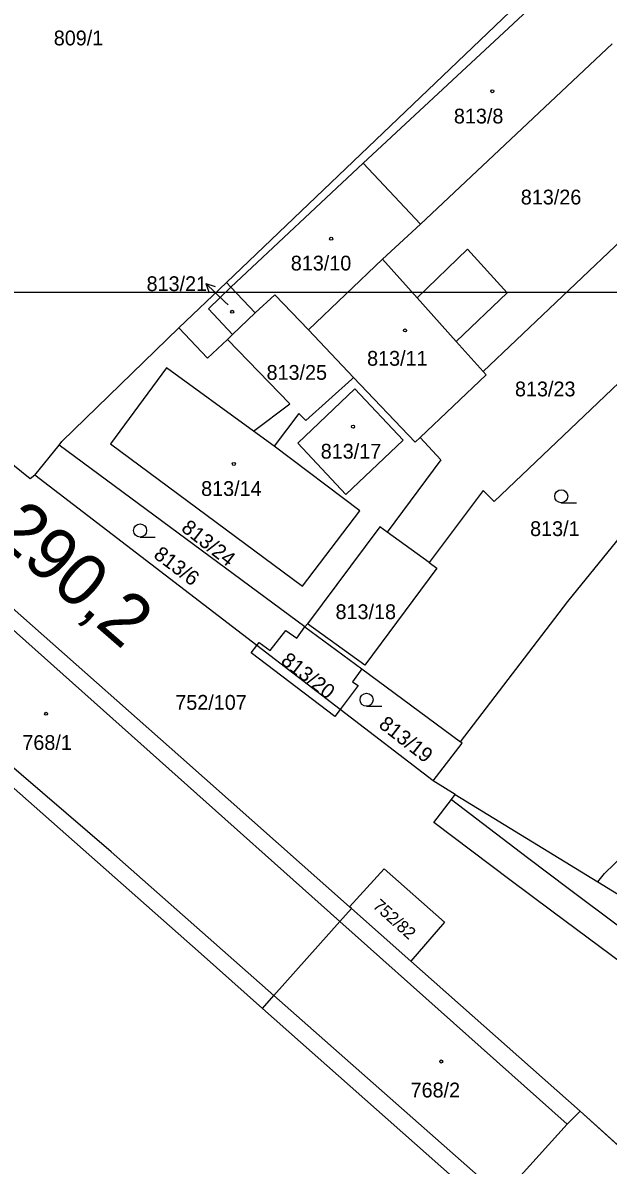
# Model space of a CAD drawing. Extents: x -496682 to -495907, y -1088575 to -1088018.
# Drawn here: x -496396.5 to -496329.2, y -1088264.6 to -1088133.3 of the extents above; entities that cross this region are included whole.
import ezdxf

# ---------------------------------------------------------------- set-up
doc = ezdxf.new("R2010")
doc.units = 0
for name, color, linetype in [('Hranice parcel', 7, 'Continuous'), ('Parcelní čísla', 7, 'Continuous'), ('Pop  PČ popisy', 7, 'Continuous'), ('Vnitřní kresba', 7, 'Continuous'), ('Vrstva 54', 7, 'Continuous'), ('Vrstva 63', 7, 'Continuous'), ('Vrstva 7', 7, 'Continuous'), ('Značky budov', 7, 'Continuous'), ('Značky kultur', 7, 'Continuous')]:
    doc.layers.add(name, color=color, linetype=linetype)

msp = doc.modelspace()

# ---------------------------------------------------------------- linework, layer by layer
at = {"layer": 'Hranice parcel'}
for p, q in [((-496373.06, -1088163.12), (-496321.41, -1088113.75)), ((-496333.69, -1088127.43), (-496357.36, -1088149.42)), ((-496350.76, -1088156.43), (-496328.71, -1088135.71)), ((-496357.36, -1088149.42), (-496372.55, -1088163.66)), ((-496357.36, -1088149.42), (-496350.76, -1088156.43)), ((-496355.12, -1088160.45), (-496350.76, -1088156.43)), ((-496363.63, -1088168.58), (-496355.12, -1088160.45)), ((-496372.55, -1088163.66), (-496373.06, -1088163.12)), ((-496372.55, -1088163.66), (-496369.75, -1088166.63)), ((-496372.37, -1088169.12), (-496369.75, -1088166.63)), ((-496363.63, -1088168.58), (-496358.44, -1088174.04)), ((-496367.58, -1088181.95), (-496369.94, -1088180.21)), ((-496395.1, -1088185.29), (-496392.28, -1088181.83)), ((-496364.03, -1088202.7), (-496392.28, -1088181.83)), ((-496369.57, -1088204.88), (-496395.1, -1088185.29)), ((-496349.76, -1088195.32), (-496354.58, -1088191.83)), ((-496363.73, -1088202.36), (-496364.03, -1088202.7)), ((-496364.03, -1088202.7), (-496357.48, -1088207.54)), ((-496360, -1088212.22), (-496369.57, -1088204.88)), ((-496357.48, -1088207.54), (-496346.16, -1088215.94)), ((-496349.3, -1088220.43), (-496360, -1088212.22)), ((-496346.76, -1088221.99), (-496349.3, -1088220.43)), ((-496347.19, -1088222.58), (-496346.76, -1088221.99)), ((-496346.76, -1088221.99), (-496330.37, -1088232.05)), ((-496358.69, -1088235.08), (-496358.91, -1088234.89)), ((-496358.69, -1088235.08), (-496351.85, -1088241.15)), ((-496351.85, -1088241.15), (-496332.38, -1088258.39)), ((-496325.94, -1088264.24), (-496332.38, -1088258.39))]:
    msp.add_line(p, q, dxfattribs=at)
for points in [[(-496395.1, -1088185.29), (-496395.64, -1088185.72), (-496443.22, -1088147.27)], [(-496317.24, -1088148.77), (-496320.78, -1088151.75), (-496343.54, -1088173.37)], [(-496343.54, -1088173.37), (-496346.64, -1088169.91), (-496340.77, -1088164.33), (-496345.36, -1088159.28), (-496351.12, -1088164.91), (-496355.12, -1088160.45)], [(-496392.28, -1088181.83), (-496391.98, -1088181.42), (-496378.53, -1088168.35), (-496373.06, -1088163.12)], [(-496304.04, -1088162.67), (-496318.49, -1088178.29), (-496324.77, -1088171.65), (-496342.29, -1088188.3), (-496343.55, -1088187.04), (-496349.76, -1088195.32)], [(-496372.55, -1088163.66), (-496375.14, -1088166.17), (-496372.37, -1088169.12)], [(-496369.75, -1088166.63), (-496367.5, -1088164.53), (-496363.63, -1088168.58)], [(-496436.18, -1088166.94), (-496429.51, -1088172.39), (-496378.3, -1088217.72), (-496358.91, -1088234.89)], [(-496369.94, -1088180.21), (-496365.78, -1088177.09), (-496372.95, -1088169.67), (-496372.37, -1088169.12)], [(-496369.94, -1088180.21), (-496379.95, -1088172.96), (-496386.4, -1088181.69), (-496364.31, -1088198.06), (-496357.74, -1088189.38), (-496367.58, -1088181.95)], [(-496358.44, -1088174.04), (-496358.66, -1088174.24), (-496363.93, -1088178.99), (-496364.72, -1088178.18), (-496367.58, -1088181.95)], [(-496358.44, -1088174.04), (-496351.36, -1088181.47), (-496350.8, -1088180.95)], [(-496350.8, -1088180.95), (-496343.21, -1088173.74), (-496343.54, -1088173.37)], [(-496358.3, -1088175.34), (-496364.87, -1088181.6), (-496359.32, -1088187.51), (-496352.73, -1088181.25), (-496358.3, -1088175.34)], [(-496368.91, -1088246.59), (-496375.97, -1088240.32), (-496428.63, -1088193.79), (-496444.11, -1088180.1)], [(-496346.16, -1088215.94), (-496333.82, -1088199.82), (-496318.2, -1088180.61)], [(-496350.8, -1088180.95), (-496348.4, -1088183.52), (-496354.58, -1088191.83)], [(-496354.58, -1088191.83), (-496355.42, -1088191.22), (-496363.73, -1088202.36)], [(-496349.76, -1088195.32), (-496348.88, -1088195.96), (-496357.15, -1088207.11), (-496363.73, -1088202.36)], [(-496330.37, -1088232.05), (-496329.58, -1088231.08), (-496327.35, -1088228.88), (-496319.53, -1088220.58), (-496313.61, -1088214.48), (-496300.1, -1088201.57), (-496296.45, -1088198.31)], [(-496369.57, -1088204.88), (-496369.28, -1088204.51), (-496368.03, -1088205.43), (-496366.23, -1088203.15), (-496364.97, -1088204.01), (-496364.03, -1088202.7)], [(-496357.48, -1088207.54), (-496358.57, -1088209.03), (-496357.92, -1088209.48), (-496360, -1088212.22)], [(-496349.3, -1088220.43), (-496345.96, -1088216.09), (-496346.16, -1088215.94)], [(-496313.9, -1088251.57), (-496335.64, -1088235.39), (-496340.47, -1088231.82), (-496349.2, -1088225.23), (-496347.19, -1088222.58)], [(-496347.19, -1088222.58), (-496338.46, -1088229.24), (-496333.64, -1088232.87), (-496316.4, -1088245.74), (-496315, -1088246.3), (-496313.02, -1088246.35), (-496311.19, -1088245.56), (-496310.18, -1088244.79)], [(-496358.91, -1088234.89), (-496354.93, -1088230.54), (-496348.01, -1088236.66), (-496351.85, -1088241.15)], [(-496330.37, -1088232.05), (-496312.02, -1088243.31), (-496311.81, -1088243.59)], [(-496368.91, -1088246.59), (-496367.6, -1088245.11), (-496360.03, -1088236.59), (-496358.69, -1088235.08)], [(-496332.38, -1088258.39), (-496333.89, -1088259.9), (-496341.4, -1088268.22), (-496342.71, -1088269.83), (-496368.91, -1088246.59)]]:
    msp.add_lwpolyline(points, dxfattribs=at)
at = {"layer": 'Pop  PČ popisy'}
for p, q in [((-496373.26, -1088165.34), (-496375.42, -1088163.26)), ((-496375.42, -1088163.26), (-496374.35, -1088163.59)), ((-496375.42, -1088163.26), (-496375.05, -1088164.31)), ((-496372.87, -1088165.71), (-496373.26, -1088165.34))]:
    msp.add_line(p, q, dxfattribs=at)
at = {"layer": 'Vnitřní kresba'}
for p, q in [((-496351.12, -1088164.91), (-496346.64, -1088169.91)), ((-496375.24, -1088171.83), (-496378.53, -1088168.35)), ((-496372.95, -1088169.67), (-496375.24, -1088171.83)), ((-496360.03, -1088236.59), (-496407.27, -1088194.48)), ((-496386.33, -1088228.59), (-496415.31, -1088203.69)), ((-496370.22, -1088205.69), (-496369.57, -1088204.88)), ((-496360.6, -1088213.02), (-496370.22, -1088205.69)), ((-496360, -1088212.22), (-496360.6, -1088213.02)), ((-496386.33, -1088228.59), (-496367.6, -1088245.11)), ((-496360.03, -1088236.59), (-496333.89, -1088259.9)), ((-496367.6, -1088245.11), (-496341.4, -1088268.22))]:
    msp.add_line(p, q, dxfattribs=at)
at = {"layer": 'Vrstva 54'}
msp.add_lwpolyline([(-496428.63, -1088193.79), (-496375.97, -1088240.32), (-496368.91, -1088246.59), (-496342.71, -1088269.83), (-496341.4, -1088268.22), (-496333.89, -1088259.9), (-496332.38, -1088258.39), (-496325.94, -1088264.24), (-496332.44, -1088271.21), (-496324.32, -1088278.18), (-496327.63, -1088281.05), (-496295.37, -1088310.06), (-496296.07, -1088310.84), (-496290.49, -1088315.87), (-496286.66, -1088311.63), (-496280.68, -1088316.78), (-496283.68, -1088320.49), (-496250.52, -1088349.65), (-496235.04, -1088333.66)], dxfattribs=at)
at = {"layer": 'Vrstva 63'}
msp.add_lwpolyline([(-496137.35, -1088164.24), (-496137.35, -1088461.24), (-496557.35, -1088461.24), (-496557.35, -1088164.24)], close=True, dxfattribs=at)
at = {"layer": 'Značky budov'}
for centre in [(-496342.5, -1088141.14), (-496361.02, -1088158.1), (-496372.4, -1088166.5), (-496352.53, -1088168.64), (-496358.51, -1088179.71), (-496372.21, -1088183.99), (-496393.79, -1088212.71), (-496348.37, -1088252.69)]:
    msp.add_circle(centre, 0.175, dxfattribs=at)
at = {"layer": 'Značky kultur'}
for p, q in [((-496334.57, -1088188.46), (-496332.82, -1088188.46)), ((-496382.99, -1088192.39), (-496381.24, -1088192.39)), ((-496356.95, -1088211.85), (-496355.2, -1088211.85))]:
    msp.add_line(p, q, dxfattribs=at)
for centre in [(-496334.57, -1088187.71), (-496382.99, -1088191.64), (-496356.95, -1088211.1)]:
    msp.add_circle(centre, 0.75, dxfattribs=at)

# ---------------------------------------------------------------- texts
at = {"layer": 'Parcelní čísla'}
for s, p in [('809/1', (-496392.91, -1088135.87)), ('813/8', (-496346.91, -1088144.85)), ('813/26', (-496339.22, -1088154.16)), ('813/10', (-496365.66, -1088161.75)), ('813/21', (-496382.24, -1088164.12)), ('813/11', (-496356.89, -1088172.7)), ('813/25', (-496368.45, -1088174.32)), ('813/23', (-496339.89, -1088176.22)), ('813/17', (-496362.22, -1088183.38)), ('813/14', (-496375.97, -1088187.67)), ('813/1', (-496338.15, -1088192.28)), ('813/18', (-496360.52, -1088201.83)), ('752/107', (-496378.94, -1088212.25)), ('768/1', (-496396.52, -1088216.87)), ('768/2', (-496351.89, -1088256.82))]:
    msp.add_text(s, height=1.7, dxfattribs=at).set_placement(p)
for s, height, rotation, p in [('813/24', 1.7, 322, (-496378.37, -1088191.6)), ('813/6', 1.7, 323, (-496381.55, -1088194.68)), ('813/20', 1.7, 322, (-496366.92, -1088206.85)), ('813/19', 1.7, 322, (-496355.67, -1088214.17)), ('752/82', 1.4, 318, (-496356.33, -1088234.92))]:
    msp.add_text(s, height=height, rotation=rotation, dxfattribs=at).set_placement(p)
at = {"layer": 'Vrstva 7'}
msp.add_text('290,2', height=6, rotation=318.9438, dxfattribs=at).set_placement((-496400.07, -1088192.24))

doc.saveas('drawing.dxf')
